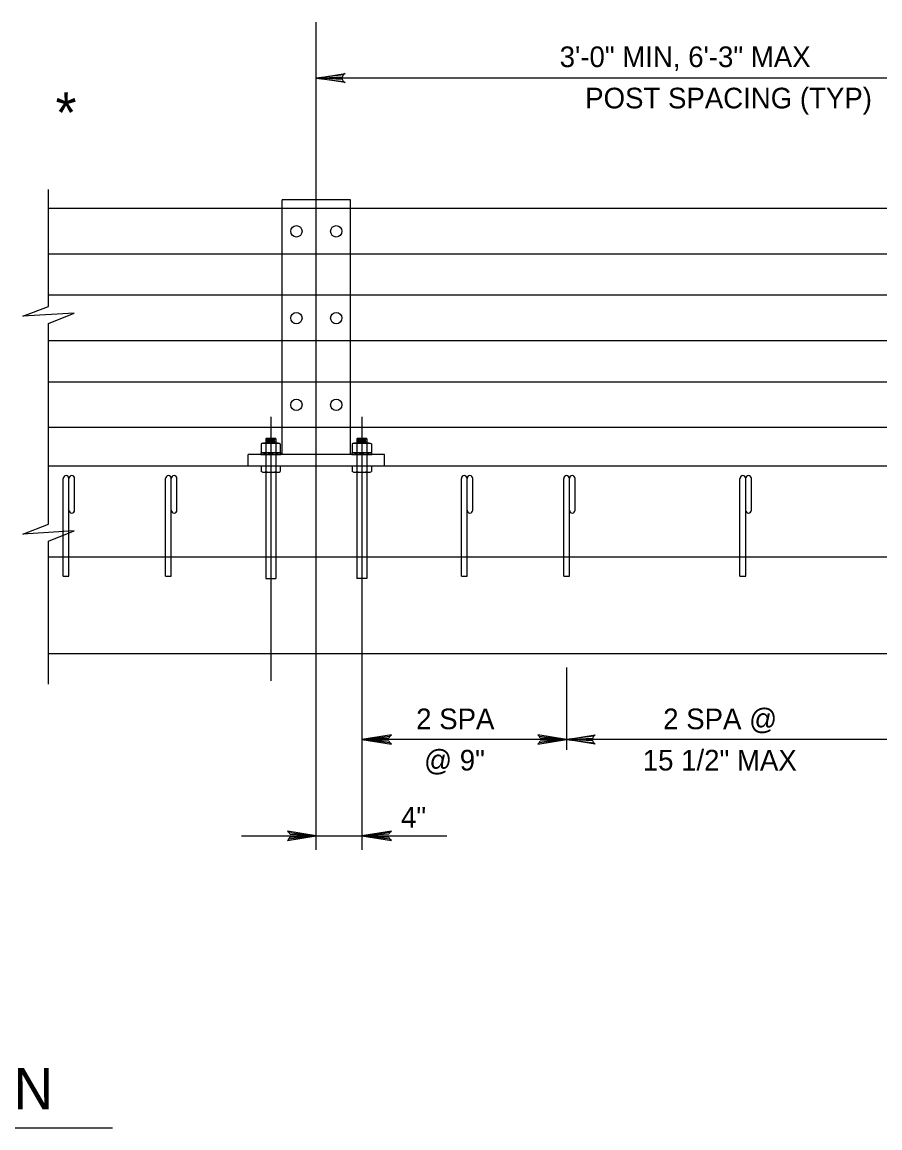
# Model space of a CAD drawing. Extents: x 641054 to 641910, y 298137 to 299325.
# Drawn here: x 641408.6 to 641533.3, y 299026.1 to 299186.7 of the extents above; entities that cross this region are included whole.
import ezdxf

# ---------------------------------------------------------------- set-up
doc = ezdxf.new("R2010")
doc.units = 0
for name, color, linetype in [('1', 7, 'Continuous'), ('2', 7, 'Continuous'), ('Default', 7, 'Continuous')]:
    doc.layers.add(name, color=color, linetype=linetype)

msp = doc.modelspace()

# ---------------------------------------------------------------- linework, layer by layer
at = {"layer": '1'}
for p, q in [((641444.05, 299126.17), (641444.17, 299126.29)), ((641444.05, 299126.17), (641444.05, 299125.57)), ((641444.05, 299126.17), (641445.49, 299126.17)), ((641444.16, 299125.99), (641445.38, 299125.99)), ((641444.17, 299126.29), (641445.37, 299126.29)), ((641445.49, 299126.17), (641445.37, 299126.29)), ((641445.49, 299126.17), (641445.49, 299125.57)), ((641457.28, 299126.17), (641457.4, 299126.29)), ((641457.28, 299126.17), (641457.28, 299125.57)), ((641457.28, 299126.17), (641458.73, 299126.17)), ((641457.4, 299126.29), (641458.61, 299126.29)), ((641457.4, 299125.99), (641458.61, 299125.99)), ((641458.73, 299126.17), (641458.61, 299126.29)), ((641458.73, 299126.17), (641458.73, 299125.57)), ((641443.57, 299125.57), (641443.38, 299125.46)), ((641443.38, 299125.46), (641443.38, 299124.25)), ((641443.57, 299125.57), (641445.98, 299125.57)), ((641444.05, 299125.81), (641445.49, 299125.81)), ((641444.05, 299125.46), (641444.05, 299124.25)), ((641444.06, 299125.77), (641444.06, 299105.88)), ((641444.16, 299125.63), (641445.38, 299125.63)), ((641445.49, 299125.46), (641445.49, 299124.25)), ((641445.5, 299125.77), (641445.5, 299105.88)), ((641445.98, 299125.57), (641446.16, 299125.46)), ((641446.16, 299125.46), (641446.16, 299124.25)), ((641456.8, 299125.57), (641456.61, 299125.46)), ((641456.61, 299125.46), (641456.61, 299124.25)), ((641456.8, 299125.57), (641459.21, 299125.57)), ((641457.28, 299125.81), (641458.73, 299125.81)), ((641457.28, 299125.77), (641457.28, 299105.88)), ((641457.28, 299125.46), (641457.28, 299124.25)), ((641457.4, 299125.63), (641458.61, 299125.63)), ((641458.73, 299125.77), (641458.73, 299105.88)), ((641458.73, 299125.46), (641458.73, 299124.25)), ((641459.21, 299125.57), (641459.4, 299125.46)), ((641459.4, 299125.46), (641459.4, 299124.25)), ((641443.57, 299124.14), (641443.38, 299124.25)), ((641445.98, 299124.14), (641446.16, 299124.25)), ((641456.8, 299124.14), (641456.61, 299124.25)), ((641459.21, 299124.14), (641459.4, 299124.25)), ((641443.38, 299122.24), (641443.38, 299121.45)), ((641446.16, 299122.24), (641443.38, 299122.24)), ((641443.57, 299121.34), (641443.38, 299121.45)), ((641443.57, 299121.34), (641445.98, 299121.34)), ((641444.05, 299122.24), (641444.05, 299121.45)), ((641445.49, 299122.24), (641445.49, 299121.45)), ((641445.98, 299121.34), (641446.16, 299121.45)), ((641446.16, 299122.24), (641446.16, 299121.45)), ((641456.61, 299122.24), (641456.61, 299121.45)), ((641459.4, 299122.24), (641456.61, 299122.24)), ((641456.8, 299121.34), (641456.61, 299121.45)), ((641456.8, 299121.34), (641459.21, 299121.34)), ((641457.28, 299122.24), (641457.28, 299121.45)), ((641458.73, 299122.24), (641458.73, 299121.45)), ((641459.21, 299121.34), (641459.4, 299121.45)), ((641459.4, 299122.24), (641459.4, 299121.45)), ((641444.06, 299105.88), (641445.5, 299105.88)), ((641458.73, 299105.88), (641457.28, 299105.88))]:
    msp.add_line(p, q, dxfattribs=at)
for points in [[(641446.22, 299123.9), (641446.22, 299124.14), (641443.32, 299124.14), (641443.32, 299123.9)], [(641459.45, 299123.9), (641459.45, 299124.14), (641456.56, 299124.14), (641456.56, 299123.9)]]:
    msp.add_lwpolyline(points, close=True, dxfattribs=at)
for points in [[(641462.09, 299083.01), (641461.94, 299082.72), (641458.01, 299082.5), (641462.09, 299083.01), (641462.3, 299083.19), (641458.01, 299082.5), (641461.94, 299082.31), (641462.08, 299082.01), (641458.01, 299082.5), (641462.3, 299081.82), (641462.08, 299082.01)], [(641462.09, 299069.03), (641461.94, 299068.73), (641458.01, 299068.52), (641462.09, 299069.03), (641462.3, 299069.21), (641458.01, 299068.52), (641461.94, 299068.32), (641462.08, 299068.03), (641458.01, 299068.52), (641462.3, 299067.83), (641462.08, 299068.03)]]:
    msp.add_lwpolyline(points, dxfattribs=at)
for centre, radius, start, end in [((641443.71, 299124.99), 0.573, 54.2974, 89.9999), ((641444.77, 299123.08), 2.48, 73.0653, 106.9335), ((641445.83, 299124.99), 0.573, 89.9993, 125.7017), ((641456.95, 299124.99), 0.573, 54.2974, 89.9999), ((641458, 299123.08), 2.48, 73.0653, 106.9335), ((641459.06, 299124.99), 0.573, 89.9993, 125.7017), ((641443.71, 299124.72), 0.573, 269.9985, 305.701), ((641444.77, 299126.63), 2.48, 253.0634, 286.9317), ((641445.83, 299124.72), 0.573, 234.2959, 269.9983), ((641456.95, 299124.72), 0.573, 269.9985, 305.701), ((641458, 299126.63), 2.48, 253.0634, 286.9317), ((641459.06, 299124.72), 0.573, 234.2959, 269.9983), ((641443.71, 299121.91), 0.573, 269.9985, 305.701), ((641444.77, 299123.82), 2.48, 253.0634, 286.9317), ((641445.83, 299121.91), 0.573, 234.2959, 269.9983), ((641456.95, 299121.91), 0.573, 269.9985, 305.701), ((641458, 299123.82), 2.48, 253.0634, 286.9317), ((641459.06, 299121.91), 0.573, 234.2959, 269.9983)]:
    msp.add_arc(centre, radius, start, end, dxfattribs=at)
at = {"layer": '2'}
for p, q in [((641635.24, 299159.65), (641412.45, 299159.65)), ((641635.24, 299153.04), (641412.45, 299153.04)), ((641635.24, 299147.05), (641412.45, 299147.05)), ((641635.24, 299140.43), (641412.45, 299140.43)), ((641635.24, 299134.44), (641412.45, 299134.44)), ((641635.24, 299127.82), (641412.45, 299127.82)), ((641414.6, 299106.23), (641415.43, 299106.23)), ((641429.48, 299106.23), (641430.31, 299106.23)), ((641472.48, 299106.23), (641473.3, 299106.23)), ((641487.36, 299106.23), (641488.18, 299106.23)), ((641512.98, 299106.23), (641513.81, 299106.23)), ((641366.83, 299026.07), (641421.78, 299026.07))]:
    msp.add_line(p, q, dxfattribs=at)
for points in [[(641455.36, 299178.11), (641455.22, 299178.4), (641451.39, 299178.61), (641455.36, 299178.11), (641455.57, 299177.94), (641451.39, 299178.61), (641455.21, 299178.8), (641455.35, 299179.09), (641451.39, 299178.61), (641455.57, 299179.28), (641455.35, 299179.09)], [(641483.8, 299082), (641483.94, 299082.29), (641487.77, 299082.5), (641483.8, 299082), (641483.59, 299081.83), (641487.77, 299082.5), (641483.95, 299082.69), (641483.81, 299082.97), (641487.77, 299082.5), (641483.59, 299083.17), (641483.81, 299082.97)], [(641491.74, 299082), (641491.59, 299082.29), (641487.77, 299082.5), (641491.74, 299082), (641491.95, 299081.83), (641487.77, 299082.5), (641491.59, 299082.69), (641491.73, 299082.97), (641487.77, 299082.5), (641491.95, 299083.17), (641491.73, 299082.97)], [(641447.42, 299068.02), (641447.57, 299068.3), (641451.39, 299068.52), (641447.42, 299068.02), (641447.21, 299067.84), (641451.39, 299068.52), (641447.57, 299068.7), (641447.43, 299068.99), (641451.39, 299068.52), (641447.21, 299069.18), (641447.43, 299068.99)]]:
    msp.add_lwpolyline(points, dxfattribs=at)
at = {"layer": 'Default'}
for p, q in [((641451.39, 299066.46), (641451.39, 299186.74)), ((641625.01, 299178.61), (641451.39, 299178.61)), ((641412.45, 299145.41), (641412.45, 299162.4)), ((641446.43, 299159.65), (641446.43, 299160.89)), ((641456.35, 299160.89), (641446.43, 299160.89)), ((641456.35, 299159.65), (641456.35, 299160.89)), ((641446.43, 299153.04), (641446.43, 299159.65)), ((641456.35, 299153.04), (641456.35, 299159.65)), ((641446.43, 299147.05), (641446.43, 299153.04)), ((641456.35, 299147.05), (641456.35, 299153.04)), ((641446.43, 299140.43), (641446.43, 299147.05)), ((641456.35, 299140.43), (641456.35, 299147.05)), ((641412.45, 299113.78), (641412.45, 299142.93)), ((641446.43, 299134.44), (641446.43, 299140.43)), ((641456.35, 299134.44), (641456.35, 299140.43)), ((641446.43, 299127.83), (641446.43, 299134.44)), ((641456.35, 299127.83), (641456.35, 299134.44)), ((641444.77, 299129.37), (641444.77, 299091.05)), ((641458.01, 299129.37), (641458.01, 299066.46)), ((641446.43, 299123.9), (641446.43, 299127.82)), ((641446.43, 299123.9), (641446.43, 299127.82)), ((641456.35, 299123.9), (641456.35, 299127.82)), ((641456.35, 299123.9), (641456.35, 299127.82)), ((641461.31, 299123.9), (641441.47, 299123.9)), ((641441.47, 299122.24), (641441.47, 299123.9)), ((641461.31, 299122.24), (641461.31, 299123.9)), ((641625.01, 299122.24), (641412.45, 299122.24)), ((641414.6, 299106.23), (641414.6, 299120.43)), ((641415.43, 299106.23), (641415.43, 299120.43)), ((641416.25, 299115.82), (641416.25, 299120.43)), ((641429.48, 299106.23), (641429.48, 299120.43)), ((641430.31, 299106.23), (641430.31, 299120.43)), ((641431.13, 299115.82), (641431.13, 299120.43)), ((641472.48, 299106.23), (641472.48, 299120.43)), ((641473.3, 299106.23), (641473.3, 299120.43)), ((641474.13, 299115.82), (641474.13, 299120.43)), ((641487.36, 299106.23), (641487.36, 299120.43)), ((641488.18, 299106.23), (641488.18, 299120.43)), ((641489.01, 299115.82), (641489.01, 299120.43)), ((641512.98, 299106.23), (641512.98, 299120.43)), ((641513.81, 299106.23), (641513.81, 299120.43)), ((641514.64, 299115.82), (641514.64, 299120.43)), ((641414.6, 299118.12), (641414.6, 299118.95)), ((641429.48, 299118.12), (641429.48, 299118.95)), ((641472.48, 299118.12), (641472.48, 299118.95)), ((641487.36, 299118.12), (641487.36, 299118.95)), ((641512.98, 299118.12), (641512.98, 299118.95)), ((641414.6, 299114.61), (641414.6, 299115.43)), ((641429.48, 299114.61), (641429.48, 299115.43)), ((641472.48, 299114.61), (641472.48, 299115.43)), ((641487.36, 299114.61), (641487.36, 299115.43)), ((641512.98, 299114.61), (641512.98, 299115.43)), ((641412.45, 299090.56), (641412.45, 299111.3)), ((641625.01, 299109.02), (641412.45, 299109.02)), ((641625.01, 299094.96), (641412.45, 299094.96)), ((641487.77, 299092.98), (641487.77, 299080.98)), ((641568.79, 299082.5), (641458.01, 299082.5)), ((641440.52, 299068.52), (641470.38, 299068.52))]:
    msp.add_line(p, q, dxfattribs=at)
for points in [[(641412.45, 299142.93), (641416.17, 299144.44), (641408.73, 299143.99), (641412.45, 299145.41)], [(641412.45, 299111.3), (641416.17, 299112.81), (641408.73, 299112.36), (641412.45, 299113.78)]]:
    msp.add_lwpolyline(points, dxfattribs=at)
for centre in [(641448.5, 299156.34), (641454.29, 299156.34), (641448.5, 299143.73), (641454.29, 299143.73), (641448.5, 299131.13), (641454.29, 299131.13)]:
    msp.add_circle(centre, 0.826, dxfattribs=at)
for centre, start, end in [((641415.01, 299120.43), 0, 180), ((641415.84, 299120.43), 0, 180), ((641429.89, 299120.43), 0, 180), ((641430.72, 299120.43), 0, 180), ((641472.89, 299120.43), 0, 180), ((641473.72, 299120.43), 0, 180), ((641487.77, 299120.43), 0, 180), ((641488.6, 299120.43), 0, 180), ((641513.4, 299120.43), 0, 180), ((641514.22, 299120.43), 0, 180), ((641415.84, 299115.82), 180, 0), ((641430.72, 299115.82), 180, 0), ((641473.72, 299115.82), 180, 0), ((641488.6, 299115.82), 180, 0), ((641514.22, 299115.82), 180, 0)]:
    msp.add_arc(centre, 0.413, start, end, dxfattribs=at)

# ---------------------------------------------------------------- texts
at = {"layer": '2'}
for s, height, p in [('3\'-0" MIN, 6\'-3" MAX', 3.0001, (641486.77, 299180.2)), ('*', 5.88, (641413.48, 299170.65)), ('POST SPACING (TYP)', 3.0001, (641490.48, 299174.2)), ('2 SPA', 3, (641465.91, 299084)), ('2 SPA @', 3, (641501.82, 299084)), ('@ 9"', 3, (641467.06, 299078)), ('15 1/2" MAX', 3.0001, (641498.85, 299078)), ('4"', 3, (641463.7, 299069.71)), ('ELEVATION', 6, (641368.12, 299028.77))]:
    msp.add_text(s, height=height, dxfattribs=at).set_placement(p)

doc.saveas('drawing.dxf')
